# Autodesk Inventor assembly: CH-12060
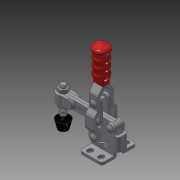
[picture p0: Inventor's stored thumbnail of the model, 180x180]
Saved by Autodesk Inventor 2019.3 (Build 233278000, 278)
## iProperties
Company: Î¢ÈíÖÐ¹ú
Created: 2015-08
Part Number: CH-12060
Material: Ogólny
Description: STEP AP203
Document SubType Name: Assembly
Designer: CADENGINEERING4
Stock Number: DOCISK PIONOWY
Sending System: SolidWorks 2012
Preprocessor: SwSTEP 2.0
Title: CH-12060.STEP
Author: Î¢ÈíÓÃ»§
Revision Number: ÈÎºÎ
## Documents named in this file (10)
- D:\Vault_2016\Projekty\Clamptek\STRONA\Vertical toggle clamp\CH-12060\CH-12060_ZAMKNIETY.iam
- D:\Vault_2016\Projekty\Clamptek\STRONA\Vertical toggle clamp\CH-12060\CH-12050-01 FLANGED BASE.ipt
- D:\Vault_2016\Projekty\Clamptek\STRONA\Vertical toggle clamp\CH-12060\CH-12050-04 CONNECTING-PLATE.ipt
- D:\Vault_2016\Projekty\Clamptek\STRONA\Vertical toggle clamp\CH-12060\CH-12050-03 STRAIGHT HANDLE.ipt
- D:\Vault_2016\Projekty\Clamptek\STRONA\Vertical toggle clamp\CH-12060\CH-12050-06.ipt
- D:\Vault_2016\Projekty\Clamptek\STRONA\Vertical toggle clamp\CH-12060\CH-12050-05.ipt
- D:\Vault_2016\Projekty\Clamptek\STRONA\Vertical toggle clamp\CH-12060\CH-FC-14134 Nut.ipt
- D:\Vault_2016\Projekty\Clamptek\STRONA\Vertical toggle clamp\CH-12060\CH-FC-14134 SPINDLE SUPPLIED.ipt
- D:\Vault_2016\Projekty\Clamptek\STRONA\Vertical toggle clamp\CH-12060\CH-12050-07.ipt
- D:\Vault_2016\Projekty\Clamptek\STRONA\Vertical toggle clamp\CH-12060\CH-12060-02 SOLID BAR_Ä¬ÈÏ_°´¼Ó¹¤_.ipt
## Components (12 placed, 12 different names)
1. CH-12050-01 FLANGED BASE_1
2. CH-12050-04 CONNECTING-PLATE_2
3. CH-12050-03 STRAIGHT HANDLE_3
4. CH-12050-06_4
5. CH-12050-06_5
6. CH-12050-05_6
7. CH-FC-14134 Nut_7
8. CH-FC-14134 SPINDLE SUPPLIED_8
9. CH-FC-14134 Nut_9
10. CH-12050-07_10
11. CH-12050-07_11
12. CH-12060-02 SOLID BAR_Ä¬ÈÏ<°´¼Ó¹¤>_12
